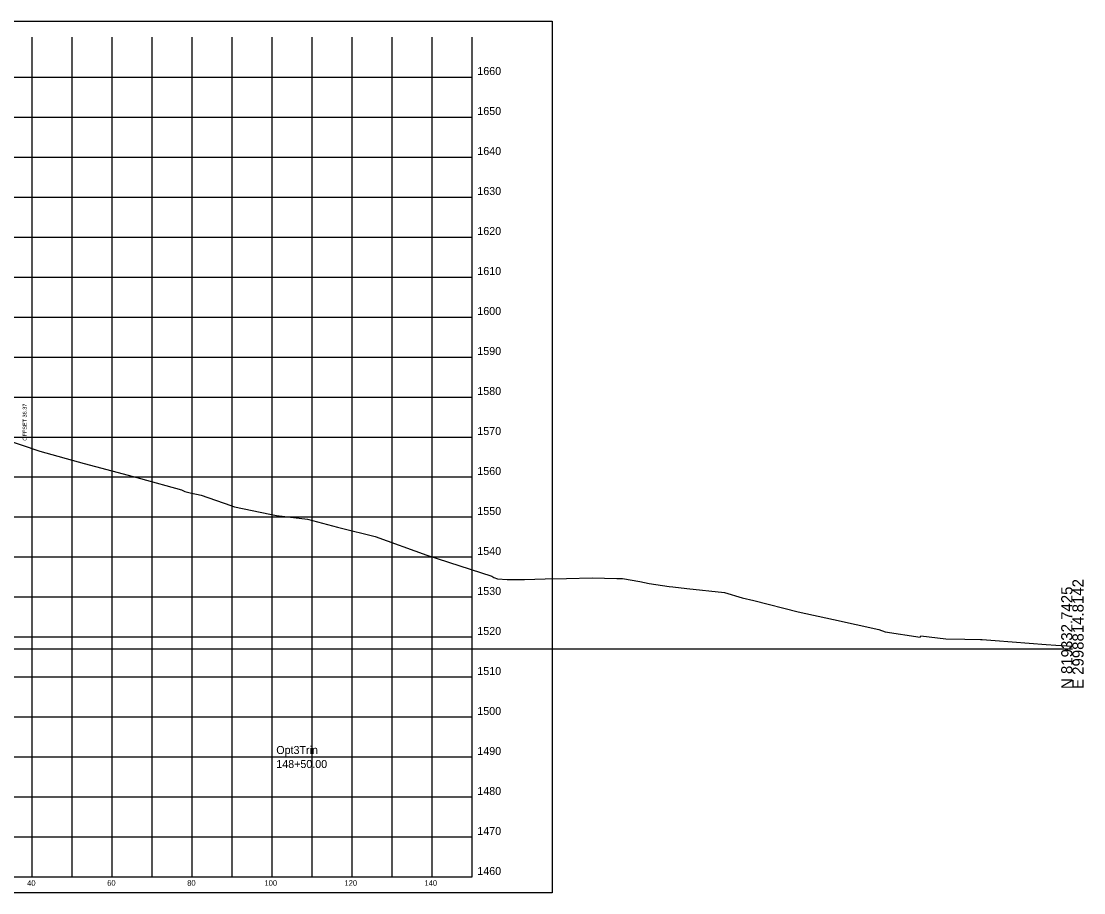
# Model space of a CAD drawing. Extents: x -26 to 603, y -10 to 4805.
# Drawn here: x 337.2 to 602.8, y 2939.1 to 3156.9 of the extents above; entities that cross this region are included whole.
import ezdxf

# ---------------------------------------------------------------- set-up
doc = ezdxf.new("R2010")
doc.units = 0
for name, color, linetype in [('DESIGN - SHEET - Corner Text', 7, 'Continuous'), ('DESIGN - SHEET - Light Grid', 7, 'Continuous'), ('DESIGN - SHEET - Linework', 7, 'Continuous'), ('DESIGN - SHEET - Plot Shape', 7, 'Continuous'), ('DESIGN - TYPICAL - Slope Tie Text', 7, 'Continuous'), ('DESIGN - TYPICAL - Warning Text', 7, 'Continuous'), ('SURVEY - GROUND - Top of Ground', 7, 'Continuous')]:
    doc.layers.add(name, color=color, linetype=linetype)

msp = doc.modelspace()

# ---------------------------------------------------------------- linework, layer by layer
at = {"layer": 'DESIGN - SHEET - Light Grid'}
msp.add_line((300, 3000), (600, 3000), dxfattribs=at)
at = {"layer": 'DESIGN - SHEET - Linework'}
for p, q in [((340, 2943), (340, 3153)), ((350, 2943), (350, 3153)), ((360, 2943), (360, 3153)), ((370, 2943), (370, 3153)), ((380, 2943), (380, 3153)), ((390, 2943), (390, 3153)), ((400, 2943), (400, 3153)), ((410, 2943), (410, 3153)), ((420, 2943), (420, 3153)), ((430, 2943), (430, 3153)), ((440, 2943), (440, 3153)), ((150, 3143), (450, 3143)), ((150, 3133), (450, 3133)), ((150, 3123), (450, 3123)), ((150, 3113), (450, 3113)), ((150, 3103), (450, 3103)), ((150, 3093), (450, 3093)), ((150, 3083), (450, 3083)), ((150, 3073), (450, 3073)), ((150, 3063), (450, 3063)), ((150, 3053), (450, 3053)), ((150, 3043), (450, 3043)), ((150, 3033), (450, 3033)), ((150, 3023), (450, 3023)), ((150, 3013), (450, 3013)), ((150, 3003), (450, 3003)), ((150, 2993), (450, 2993)), ((150, 2983), (450, 2983)), ((150, 2973), (450, 2973)), ((150, 2963), (450, 2963)), ((150, 2953), (450, 2953))]:
    msp.add_line(p, q, dxfattribs=at)
msp.add_lwpolyline([(150, 3153), (150, 2943), (450, 2943), (450, 3153)], dxfattribs=at)
at = {"layer": 'DESIGN - SHEET - Plot Shape'}
msp.add_lwpolyline([(130, 3156.94), (470, 3156.94), (470, 2939.06), (130, 2939.06)], close=True, dxfattribs=at)
at = {"layer": 'SURVEY - GROUND - Top of Ground'}
msp.add_lwpolyline([(317.5, 3057.68), (341.92, 3049.44), (353.01, 3046.41), (362.71, 3043.83), (367.06, 3042.6), (377.34, 3039.79), (378.14, 3039.37), (379.44, 3039), (382.18, 3038.42), (389.61, 3035.84), (390.56, 3035.56), (399.36, 3033.67), (401.03, 3033.34), (408.83, 3032.43), (416.33, 3030.46), (416.96, 3030.31), (425.71, 3028.13), (438.62, 3023.42), (454.87, 3018.23), (455.39, 3017.9), (456.29, 3017.5), (458.73, 3017.38), (461.4, 3017.4), (463.03, 3017.37), (468.19, 3017.55), (473.58, 3017.65), (480, 3017.79), (486.12, 3017.64), (487.54, 3017.61), (491.9, 3016.88), (494.21, 3016.37), (499.2, 3015.64), (500.13, 3015.5), (503.65, 3015.1), (513.01, 3014.11), (517.48, 3012.83), (520.33, 3012.14), (531.48, 3009.33), (540.28, 3007.37), (551.64, 3004.84), (553.19, 3004.28), (561.96, 3002.98), (562.1, 3003.26), (568.33, 3002.58), (573.12, 3002.47), (577.03, 3002.35), (577.43, 3002.38), (580.71, 3002.14), (593.43, 3001.1), (595.83, 3000.98), (600, 3000.73)], dxfattribs=at)

# ---------------------------------------------------------------- texts
at = {"layer": 'DESIGN - SHEET - Corner Text'}
for s, height, p in [('1660', 2, (451.25, 3143.5)), ('1650', 2, (451.25, 3133.5)), ('1640', 2, (451.25, 3123.5)), ('1630', 2, (451.25, 3113.5)), ('1620', 2, (451.25, 3103.5)), ('1610', 2, (451.25, 3093.5)), ('1600', 2, (451.25, 3083.5)), ('1590', 2, (451.25, 3073.5)), ('1580', 2, (451.25, 3063.5)), ('1570', 2, (451.25, 3053.5)), ('1560', 2, (451.25, 3043.5)), ('1550', 2, (451.25, 3033.5)), ('1540', 2, (451.25, 3023.5)), ('1530', 2, (451.25, 3013.5)), ('1520', 2, (451.25, 3003.5)), ('1510', 2, (451.25, 2993.5)), ('1500', 2, (451.25, 2983.5)), ('1490', 2, (451.25, 2973.5)), ('1480', 2, (451.25, 2963.5)), ('1470', 2, (451.25, 2953.5)), ('1460', 2, (451.25, 2943.5)), ('40', 1.4, (338.74, 2940.8)), ('60', 1.4, (358.74, 2940.8)), ('80', 1.4, (378.74, 2940.8)), ('100', 1.4, (398.06, 2940.8)), ('120', 1.4, (418.06, 2940.8)), ('140', 1.4, (438.06, 2940.8))]:
    msp.add_text(s, height=height, dxfattribs=at).set_placement(p)
at = {"layer": 'DESIGN - SHEET - Light Grid'}
for s, p in [('E 2998814.8142', (602.8, 2990)), ('N 819332.7425', (600, 2990))]:
    msp.add_text(s, height=2.8, rotation=90, dxfattribs=at).set_placement(p)
at = {"layer": 'DESIGN - TYPICAL - Slope Tie Text'}
msp.add_text('OFFSET 36.37', height=1, rotation=90, dxfattribs=at).set_placement((338.62, 3052.06))
at = {"layer": 'DESIGN - TYPICAL - Warning Text'}
for s, p in [('Opt3Trin', (401, 2973.75)), ('148+50.00', (401, 2970.25))]:
    msp.add_text(s, height=2, dxfattribs=at).set_placement(p)

doc.saveas('drawing.dxf')
